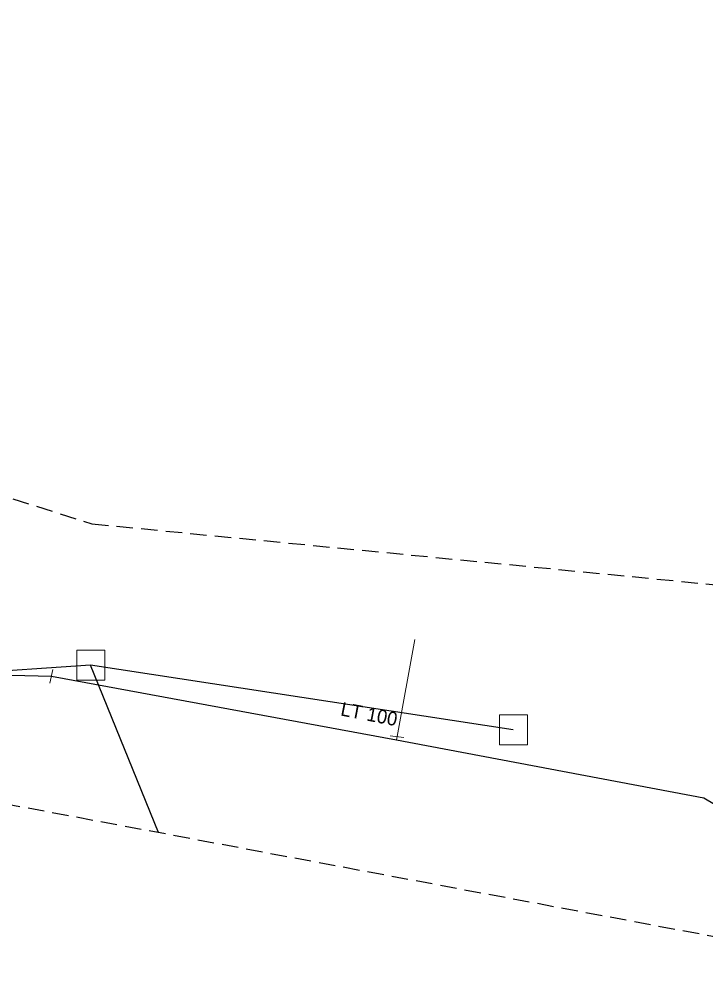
# Model space of a CAD drawing. Extents: x -688691 to -688449, y -974248 to -973966.
# Drawn here: x -688549.3 to -688499.2, y -974034.9 to -973965.6 of the extents above; entities that cross this region are included whole.
import ezdxf

# ---------------------------------------------------------------- set-up
doc = ezdxf.new("R2010")
doc.units = 0
doc.header["$LTSCALE"] = 0.4
doc.linetypes.add('MEDIUM_DASHED', pattern=[4.5, 3, -1.5])
for name, color, linetype, lineweight in [('1', 7, 'MEDIUM_DASHED', 25), ('13', 7, 'Continuous', 13), ('14', 7, 'Continuous', 25), ('17', 7, 'Continuous', 25), ('22', 7, 'Continuous', 13), ('34', 7, 'Continuous', 13)]:
    doc.layers.add(name, color=color, linetype=linetype, lineweight=lineweight)

msp = doc.modelspace()

# ---------------------------------------------------------------- linework, layer by layer
at = {"layer": '1'}
msp.add_lwpolyline([(-688492.642, -974007.422), (-688474.778, -973965.553), (-688449.099, -973975.602), (-688472.545, -974030.309), (-688492.642, -974033.659), (-688555.165, -974021.936), (-688650.066, -974071.061), (-688624.387, -974128.002), (-688613.222, -974120.745), (-688593.125, -974162.055), (-688604.29, -974165.404), (-688581.96, -974212.855), (-688565.213, -974206.156), (-688558.514, -974230.719), (-688607.64, -974248.024), (-688622.154, -974231.277), (-688607.64, -974225.136), (-688626.62, -974194.433), (-688691.376, -974059.338), (-688565.213, -973995.698), (-688544, -974002.397)], close=True, dxfattribs=at)
at = {"layer": '13'}
msp.add_line((-688521.749, -974017.925), (-688520.444, -974010.832), dxfattribs=at)
at = {"layer": '14'}
for p in [(-688513.289, -974017.427), (-688539.158, -974024.937)]:
    msp.add_line(p, (-688544.118, -974012.713), dxfattribs=at)
at = {"layer": '14', "lineweight": 13}
msp.add_line((-688521.777, -974018.152), (-688521.749, -974017.925), dxfattribs=at)
at = {"layer": '14'}
msp.add_lwpolyline([(-688544.118, -974012.713), (-688553.402, -974013.335), (-688562.069, -974015.498), (-688588.977, -974027.483)], dxfattribs=at)
at = {"layer": '17'}
for points in [[(-688582.724, -974025.561), (-688549.875, -974013.454), (-688546.964, -974013.527)], [(-688546.964, -974013.527), (-688521.777, -974018.152), (-688499.362, -974022.396), (-688496.795, -974023.937)]]:
    msp.add_lwpolyline(points, dxfattribs=at)
at = {"layer": '22'}
for points in [[(-688545.098, -974011.623), (-688543.065, -974011.623), (-688543.065, -974013.816), (-688545.098, -974013.816)], [(-688514.269, -974016.337), (-688512.236, -974016.337), (-688512.236, -974018.53), (-688514.269, -974018.53)]]:
    msp.add_lwpolyline(points, close=True, dxfattribs=at)
at = {"layer": '34'}
for p, q in [((-688546.863, -974013.037), (-688547.065, -974014.016)), ((-688522.245, -974017.863), (-688521.252, -974017.987))]:
    msp.add_line(p, q, dxfattribs=at)

# ---------------------------------------------------------------- texts
at = {"layer": '1'}
msp.add_text('LT 100', height=1, rotation=349, dxfattribs=at).set_placement((-688525.919, -974016.378))

doc.saveas('drawing.dxf')
